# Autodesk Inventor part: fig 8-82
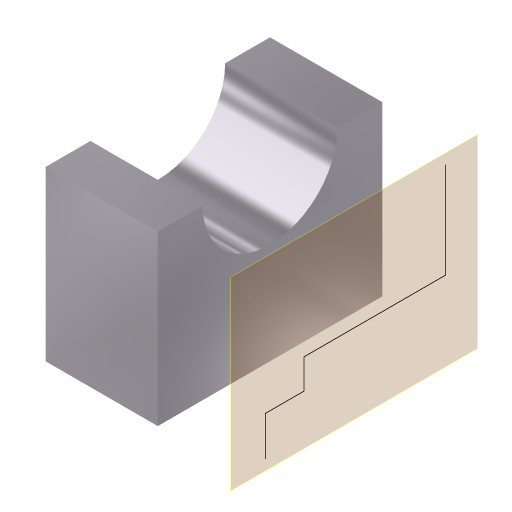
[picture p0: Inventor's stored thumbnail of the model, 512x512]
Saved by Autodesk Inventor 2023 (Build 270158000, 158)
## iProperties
Created: 2002-01
Part Number: fig 8-82
Document SubType Name: Modeling
Designer: ***
Density: 1 g/cm^3
Material: Generic
Appearance: Metal-AL-6061 (Polished)
Control State: 0
Master: False
Checked Out: False
Shininess: 77.0
Length Units: 11269
Angle Units: 11279
Time Units: 11290
Mass Units: 11283
Length Display Precision: 3
Angle Display Precision: 2
Density: 0.0
Volumn: 0.0
Area: 0.0
PropertySet Name: Model Information
Author: ***
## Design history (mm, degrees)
sketch "Sketch5"
  geometry: L1 (-22.226, 10.275)-(-14.226, 10.275); L2 (9.774, 10.275)-(17.774, 10.275); L3 (17.774, 10.275)-(17.774, -19.725); L4 (17.774, -19.725)-(-22.226, -19.725); L5 (-22.226, -19.725)-(-22.226, 10.275); A1 r 12 centre (-2.226, 10.275) between (-14.226, 10.275) and (9.774, 10.275)
  constraints: 10 end point, 2 equal length, 2 parallel, 2 point on circle, 1 centre point, 1 collinear, 1 horizontal, 1 perpendicular, 1 point on line
  dimensions: "d7" = 40 distance of L3.end L4.end; "d8" = 30 distance of L2.end L3.end; "d9" = 12 radius of A1
extrude "Extrusion2" new body sketch "Sketch5" distance "d10" = 20; taper "d11" = 0 deg
workplane "Work Plane3"
sketch "Sketch6"
  geometry: L1 (19.321, -18.091)-(12.314, -18.091); L2 (12.314, -18.091)-(12.314, -11.217); L3 (12.314, -11.217)-(7.026, -11.217); L4 (7.026, -11.217)-(7.026, 7.425); L5 (7.026, 7.425)-(7.026, 14.035); L6 (7.026, 14.035)-(-10.029, 14.035)
  constraints: 12 end point, 4 parallel, 1 horizontal, 1 perpendicular
body "Solid1"
other parameters: "d12" = 15
